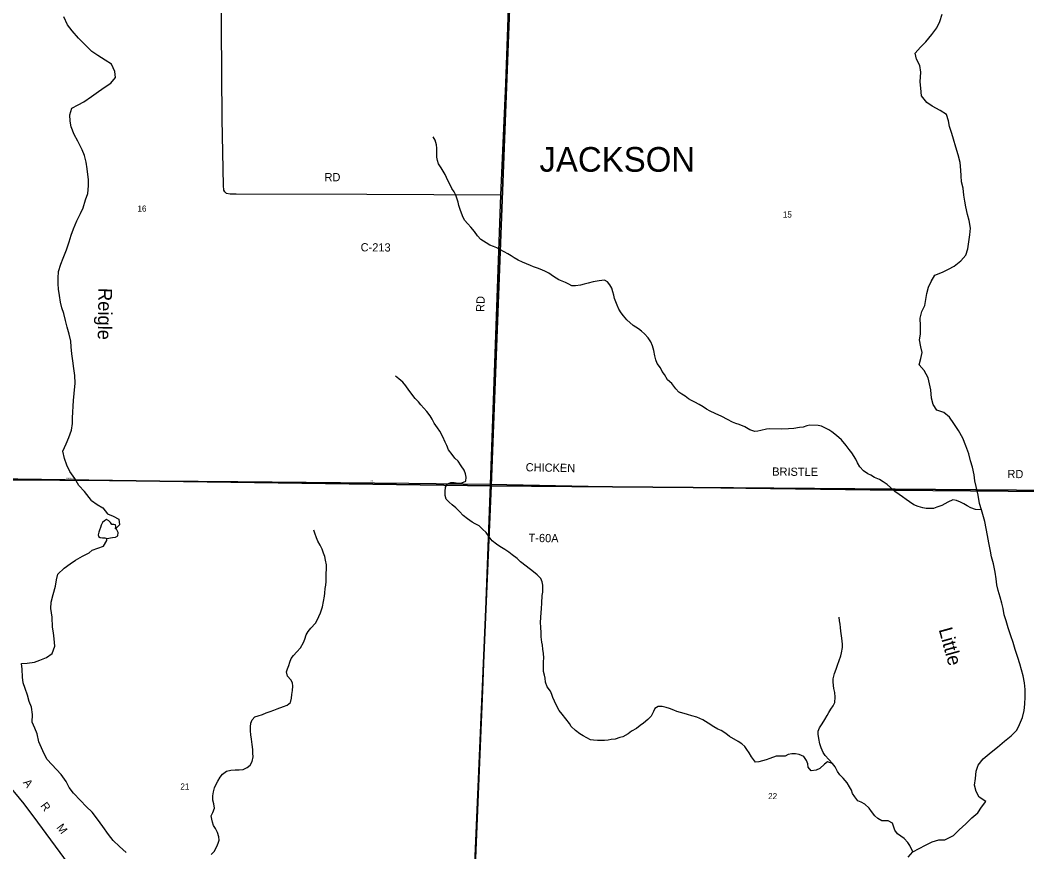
# Model space of a CAD drawing. Extents: x 1312308 to 1684953, y 460642 to 865172.
# Drawn here: x 1422870 to 1432056, y 621406 to 628989 of the extents above; entities that cross this region are included whole.
import ezdxf

# ---------------------------------------------------------------- set-up
doc = ezdxf.new("R2010")
doc.units = 0
for name, color, linetype in [('GM_X_County_Road', 7, 'Continuous'), ('GM_X_County_Road_Text', 7, 'Continuous'), ('GM_X_Minor_Lake', 7, 'Continuous'), ('GM_X_Minor_River', 7, 'Continuous'), ('GM_X_Minor_River_Text', 7, 'Continuous'), ('GM_X_Section', 7, 'Continuous'), ('GM_X_Section_Text', 7, 'Continuous'), ('GM_X_Township_Road', 7, 'Continuous'), ('GM_X_Township_Road_Text', 7, 'Continuous'), ('GM_X_Township_Subdivision', 7, 'Continuous'), ('GM_X_Township_Subdivision_Text', 7, 'Continuous'), ('GM_X_Township_Text', 7, 'Continuous')]:
    doc.layers.add(name, color=color, linetype=linetype)

msp = doc.modelspace()

# ---------------------------------------------------------------- linework, layer by layer
at = {"layer": 'GM_X_County_Road'}
for points in [[(1427257.5, 627393.2), (1426034, 627399.5), (1424841.7, 627402.6), (1424785.8, 627402), (1424754, 627408.7), (1424737.3, 627422.5), (1424728.2, 627437.8), (1424725.9, 627481), (1424712.3, 628086), (1424706.1, 628920.6), (1424700.1, 629955.3), (1424702.4, 630572.3), (1424735.3, 632468.4), (1424764.9, 634127), (1424816.2, 638179.6), (1424838.9, 639451.3), (1424867.3, 641453.3)], [(1426953, 619489.3), (1426952.1, 619516.1), (1426971.2, 619931.5), (1426996.8, 620555.9), (1427022.4, 621198.4), (1427091.4, 622876.4), (1427163, 624758.3), (1427257.5, 627393.2), (1427300.3, 628410.2), (1427360.9, 630040.4), (1427420.8, 632760.9), (1427452.2, 634128.6), (1427497.7, 636658.4), (1427531.5, 637964.6), (1427563.2, 639629.6), (1427575.5, 640318.2)], [(1425178.7, 618809.3), (1424819, 619478.2), (1424794.1, 619513.9), (1424735.3, 619588.9), (1424329.4, 620045.2), (1423843.4, 620590.6), (1423757, 620693.6), (1423588.3, 620906.4), (1423489.2, 621043.8), (1423309.8, 621294.9), (1423031.7, 621676.5), (1422907.5, 621844.7), (1422721.8, 622068.1), (1422500.6, 622334.6), (1422184.3, 622710.6), (1421710.1, 623249.4), (1421491.7, 623491.9), (1421228.6, 623784.4), (1420620.9, 624439.9), (1420252.3, 624831.1), (1420094.1, 624993.7), (1420031.9, 625057)]]:
    msp.add_lwpolyline(points, dxfattribs=at)
at = {"layer": 'GM_X_Minor_Lake'}
for points in [[(1423739.7, 624350.6), (1423742.1, 624372.6), (1423740.4, 624388.7), (1423724.5, 624391), (1423706.4, 624391.4), (1423692.8, 624409.7), (1423679, 624424.1), (1423659.2, 624434.5), (1423638.9, 624422.9), (1423622.5, 624407.3), (1423610, 624383.5), (1423601.5, 624361.6), (1423595.1, 624339.7), (1423586.6, 624319.8), (1423582.1, 624295.8), (1423585.9, 624281.7), (1423599.7, 624271.4), (1423621.7, 624268.9), (1423641.7, 624268.5), (1423659.7, 624264.1)], [(1423659.7, 624264.1), (1423711.9, 624271), (1423740.1, 624274.4), (1423762.4, 624287.9), (1423763, 624316), (1423747.6, 624348.4), (1423739.7, 624350.6)]]:
    msp.add_lwpolyline(points, dxfattribs=at)
at = {"layer": 'GM_X_Minor_River'}
for points in [[(1423520.2, 624609.8), (1423458.2, 624691.8), (1423405.6, 624745.7), (1423369.5, 624809.2), (1423323.3, 624875), (1423294.9, 624930.1), (1423274.7, 624991), (1423260.7, 625057.8), (1423289, 625127.1), (1423314.8, 625182.5), (1423339, 625249.9), (1423349, 625311.8), (1423346.5, 625362.1), (1423357.5, 625520.4), (1423361.5, 625584.5), (1423372.5, 625678.5), (1423368.6, 625748.9), (1423360.5, 625811.4), (1423350.8, 625884), (1423342.7, 625946.5), (1423336.6, 626011), (1423332.3, 626063.3), (1423318.1, 626126), (1423300.1, 626190.8), (1423283.9, 626251.6), (1423267.8, 626314.4), (1423251.3, 626365.1), (1423236.9, 626417.8), (1423228.7, 626478.3), (1423218.4, 626534.8), (1423216, 626585.1), (1423215.6, 626637.3), (1423219.5, 626697.4), (1423239.6, 626763), (1423261.4, 626818.5), (1423293.9, 626893.7), (1423316.3, 626967.2), (1423334.2, 627028.9), (1423356.1, 627086.4), (1423388.5, 627157.6), (1423420.7, 627224.8), (1423444.4, 627276.2), (1423466.8, 627349.7), (1423486.7, 627409.3), (1423494.8, 627477.3), (1423494.6, 627533.5), (1423481.7, 627634.3), (1423471.5, 627694.8), (1423457.3, 627753.5), (1423436.8, 627806.4), (1423395, 627884), (1423362.9, 627947.3), (1423334.9, 628016.5), (1423326.4, 628066.9), (1423324.2, 628125.2), (1423342.2, 628184.8), (1423399.4, 628217.1), (1423452.4, 628243.4), (1423522.2, 628291.3), (1423586, 628339.4), (1423645.5, 628379.5), (1423698.8, 628413.9), (1423738.6, 628466.8), (1423734.2, 628519.1), (1423702.2, 628588.4), (1423645.1, 628624.4), (1423580.1, 628666.7), (1423523, 628702.7), (1423456.8, 628771.1), (1423402.3, 628825.1), (1423344.1, 628891.3), (1423301.6, 628944.9), (1423267.8, 629020.2)], [(1431078.5, 628575), (1431048.2, 628632.2), (1431037.8, 628686.7), (1431085.7, 628741.3), (1431135.5, 628791.9), (1431187.8, 628858.4), (1431235.9, 628919.1), (1431261.8, 628976.4), (1431283.9, 629041.9)], [(1431912.1, 622462.2), (1431966, 622514.7), (1431987.6, 622566.2), (1432015.8, 622631.6), (1432031.8, 622695.4), (1432037.7, 622753.4), (1432041.7, 622817.6), (1432041.8, 622885.9), (1432035.7, 622946.3), (1432023.6, 623009), (1431990.8, 623118.6), (1431974.6, 623177.3), (1431950.8, 623250.4), (1431932.6, 623313.3), (1431910.4, 623374.3), (1431886.7, 623449.4), (1431866.6, 623512.3), (1431850.2, 623567), (1431839.9, 623623.6), (1431827.4, 623674.2), (1431813.1, 623728.9), (1431794.9, 623789.8), (1431782.4, 623840.4), (1431776.1, 623894.8), (1431765.9, 623955.4), (1431750.2, 624032.2), (1431734.2, 624097), (1431725.7, 624147.5), (1431710, 624222.3), (1431696, 624291.1), (1431685.9, 624353.7), (1431671.9, 624418.4), (1431643.1, 624523.8), (1431624.7, 624580.6), (1431613.1, 624657.2), (1431593.5, 624738.2), (1431581, 624788.8), (1431574.7, 624843.2), (1431558.8, 624914), (1431540.5, 624970.9), (1431526.5, 625035.6), (1431500.6, 625106.7), (1431470.7, 625177.9), (1431432.7, 625247.5), (1431390.5, 625311.1), (1431350.1, 625368.6), (1431299.2, 625410.4), (1431235.6, 625432.6), (1431201.1, 625483.9), (1431184.7, 625540.7), (1431181.1, 625617.1), (1431166.7, 625671.8), (1431156.5, 625728.3), (1431120.3, 625793.7), (1431073.8, 625845.4), (1431087.7, 625905.2), (1431099.3, 625957), (1431088.9, 626009.6), (1431074.9, 626074.3), (1431084.5, 626126.1), (1431086.9, 626202.3), (1431083, 626270.7), (1431099, 626332.4), (1431124.8, 626387.8), (1431142.3, 626497.6), (1431158.2, 626555.3), (1431183.9, 626606.7), (1431215.8, 626663.8), (1431284.9, 626689.7), (1431340, 626718), (1431393.1, 626746.4), (1431452.8, 626794.6), (1431500.6, 626845.2), (1431518.4, 626902.8), (1431534.5, 627030.8), (1431540.4, 627092.8), (1431530.6, 627163.4), (1431514.2, 627216.1), (1431498.3, 627286.9), (1431489.8, 627337.3), (1431481.5, 627391.8), (1431473.4, 627456.3), (1431459.2, 627514.9), (1431456.9, 627569.2), (1431454.5, 627621.5), (1431448.6, 627689.9), (1431430.7, 627760.7), (1431406.8, 627829.8), (1431386.9, 627902.7), (1431370.5, 627955.4), (1431350.4, 628020.3), (1431340, 628070.8), (1431323.7, 628129.5), (1431264.6, 628165.6), (1431193.5, 628204), (1431142.3, 628237.8), (1431096, 628297.5), (1431088.2, 628370), (1431083.9, 628426.3), (1431088.7, 628514.5), (1431078.5, 628575)], [(1428201, 626618.3), (1428154.8, 626613.1), (1428098.4, 626602.1), (1428054, 626590.9), (1428017.8, 626581.5), (1427983.5, 626572.1), (1427937.2, 626564.9), (1427905.1, 626567.5), (1427875.3, 626582.1), (1427847.6, 626596.7), (1427815.7, 626609.3), (1427785.9, 626621.9), (1427736.4, 626652.9), (1427694.9, 626681.8), (1427663.1, 626698.4), (1427629.3, 626713.1), (1427591.5, 626727.8), (1427555.6, 626738.5), (1427527.8, 626751.1), (1427490, 626767.8), (1427454.2, 626782.6), (1427414.4, 626799.4), (1427376.8, 626822.1), (1427349.1, 626838.7), (1427319.4, 626857.3), (1427285.6, 626876), (1427248, 626896.8), (1427218.2, 626911.4), (1427188.3, 626924), (1427154.5, 626938.6), (1427122.9, 626959.3), (1427073.3, 626988.3), (1427043.9, 627023), (1427014.6, 627061.6), (1426983.3, 627100.3), (1426955.9, 627133), (1426924.5, 627165.7), (1426907.3, 627206.1), (1426886.4, 627262.7), (1426873.1, 627299.1), (1426865.7, 627329.3), (1426858.2, 627357.6), (1426844.9, 627391.9), (1426831.5, 627422.3), (1426810.1, 627454.8), (1426792.7, 627487.2), (1426779.2, 627515.6), (1426760, 627554), (1426748.5, 627582.4), (1426729.1, 627612.8), (1426711.6, 627641.2), (1426688.3, 627679.8), (1426676.9, 627710.1), (1426673.5, 627740.3), (1426672.4, 627782.4), (1426671.1, 627820.6), (1426667.7, 627850.8), (1426656.6, 627895.1), (1426639.1, 627923.5)], [(1431643.1, 624523.8), (1431586.1, 624526.5), (1431544.3, 624541.3), (1431510.6, 624562), (1431480.9, 624578.6), (1431449.1, 624595.3), (1431415.3, 624607.9), (1431381.3, 624614.6), (1431334.7, 624593.3), (1431280, 624564.2), (1431233.5, 624547), (1431203.2, 624535.5), (1431137, 624536.7), (1431107.1, 624543.3), (1431065.2, 624554.1), (1431025.4, 624570.9), (1430985.8, 624597.7), (1430954.2, 624618.4), (1430920.5, 624641.1), (1430890.9, 624663.7), (1430851.3, 624690.6), (1430812, 624727.4), (1430782.4, 624754.1), (1430744.8, 624778.8), (1430711.2, 624799.5), (1430665.4, 624818.5), (1430631.8, 624841.2), (1430603.9, 624853.7), (1430564.3, 624878.5), (1430531, 624915.3), (1430509.7, 624953.8), (1430494.3, 624986.2), (1430459.4, 625043.1), (1430436, 625075.6), (1430408.6, 625110.3), (1430363.6, 625163.3), (1430320.3, 625202.2), (1430276.8, 625235.2), (1430249.1, 625253.7), (1430219.3, 625268.3), (1430181.6, 625287.1), (1430151.6, 625293.7), (1430075.4, 625295.1), (1430047.2, 625289.5), (1430014.9, 625278.1), (1429980.7, 625274.7), (1429930.4, 625265.6), (1429880.2, 625262.5), (1429818, 625259.6), (1429711.7, 625261.6), (1429679.6, 625260.2), (1429629.2, 625247), (1429601, 625241.5), (1429572.8, 625238), (1429529, 625252.9), (1429483.4, 625279.8), (1429429.7, 625302.9), (1429401.8, 625311.4), (1429370, 625324.1), (1429324.3, 625347), (1429272.7, 625374.1), (1429211.1, 625403.3), (1429165.4, 625424.2), (1429133.7, 625442.9), (1429102.1, 625463.5), (1429066.4, 625484.2), (1429026.7, 625505), (1428994.9, 625519.7), (1428967.2, 625536.3), (1428937.5, 625558.9), (1428907.8, 625577.5), (1428880.2, 625598.1), (1428852.7, 625628.7), (1428815.6, 625675.5), (1428776.2, 625710.4), (1428749, 625757.1), (1428729.6, 625785.5), (1428712.2, 625818), (1428682.9, 625858.7), (1428669.6, 625893), (1428662.3, 625929.3), (1428653.2, 625975.6), (1428640, 626018), (1428624.7, 626054.4), (1428599.5, 626093), (1428568.1, 626127.8), (1428538.5, 626152.4), (1428510.8, 626173), (1428463.4, 626205.9), (1428406.3, 626257.2), (1428376.9, 626291.9), (1428353.4, 626320.4), (1428332, 626354.9), (1428316.7, 626389.3), (1428293.9, 626452), (1428286.5, 626482.2), (1428277, 626510.5), (1428267.7, 626544.8), (1428250.3, 626575.2), (1428228.8, 626603.7), (1428201, 626618.3)], [(1427638.6, 623838.1), (1427633.2, 623866.3), (1427619.8, 623898.7), (1427588.4, 623931.4), (1427552.8, 623960.2), (1427487.7, 624009.5), (1427436.4, 624050.7), (1427404.9, 624081.3), (1427359.4, 624114.3), (1427327.8, 624139), (1427292.2, 624161.7), (1427246.6, 624188.7), (1427217, 624211.3), (1427177.5, 624240.2), (1427148.1, 624276.8), (1427122.9, 624317.5), (1427089.4, 624348.2), (1427057.9, 624376.9), (1427022.2, 624395.6), (1426994.5, 624412.2), (1426950.9, 624441.1), (1426911.4, 624471.9), (1426880.1, 624508.7), (1426844.7, 624543.5), (1426813.1, 624568.1), (1426785.5, 624592.7), (1426758, 624621.4), (1426748.7, 624655.7), (1426747.5, 624691.8), (1426752.3, 624731.9), (1426768.9, 624761.7), (1426799.3, 624773.2), (1426829.3, 624772.6), (1426865.3, 624765.9), (1426901.5, 624769.3), (1426935.9, 624786.7), (1426940.6, 624820.8), (1426933.3, 624853), (1426921.9, 624885.4), (1426892.7, 624926.1), (1426867.4, 624966.7), (1426835.9, 624995.4), (1426810.5, 625027.9), (1426777.3, 625070.7), (1426762, 625109.2), (1426746.6, 625139.6), (1426727.6, 625190.1), (1426700.5, 625240.8), (1426679.1, 625271.3), (1426647.9, 625314), (1426630.6, 625350.5), (1426611.1, 625381), (1426579.8, 625419.7), (1426554.4, 625452.3), (1426524.9, 625480.9), (1426505.5, 625509.4), (1426474, 625538.1), (1426415.4, 625615.4), (1426388.1, 625654.1), (1426360.7, 625688.7), (1426325.2, 625719.5), (1426295.6, 625744.1)], [(1423520.2, 624609.8), (1423573.8, 624572.8), (1423625.4, 624543.5), (1423666.3, 624488.5), (1423718, 624465.3), (1423769.5, 624438.2), (1423776.5, 624387.9), (1423739.7, 624350.6)], [(1425658.8, 623838.5), (1425661.5, 623870.6), (1425662.1, 623900.7), (1425661, 623944.9), (1425663.8, 623983), (1425664.6, 624021.2), (1425657.5, 624065.5), (1425650.2, 624099.7), (1425638.7, 624128.1), (1425625.4, 624164.4), (1425608.1, 624200.9), (1425586.8, 624239.5), (1425573.4, 624269.8), (1425558.2, 624310.3), (1425548.7, 624338.5)], [(1423527.4, 624156.2), (1423577.6, 624175.6), (1423630.1, 624192.5), (1423659.3, 624243.7), (1423659.7, 624264.1)], [(1423376.4, 624065.9), (1423437.8, 624102.1), (1423499, 624132.2), (1423527.4, 624156.2)], [(1423837.5, 621399.6), (1423774.9, 621455.9), (1423718.3, 621507.9), (1423675.9, 621563.6), (1423624, 621637.6), (1423575.8, 621703.5), (1423525.6, 621767.4), (1423473, 621819.3), (1423420.5, 621875.3), (1423356.3, 621941.7), (1423315.7, 621993.2), (1423289.3, 622048.3), (1423243.1, 622112.1), (1423116.8, 622246.8), (1423088.3, 622298), (1423065.9, 622355), (1423039.5, 622408.1), (1423023.7, 622480.9), (1423005.2, 622533.7), (1422978.8, 622586.8), (1422981, 622659.1), (1422973.1, 622725.6), (1422950.6, 622776.6), (1422938.3, 622835.2), (1422916.1, 622896.2), (1422897.6, 622947), (1422891.2, 622999.4), (1422889.4, 623069.8), (1422883, 623122.2), (1422935.3, 623124.5), (1422999.9, 623136.5), (1423050.7, 623152.9), (1423109.7, 623179), (1423163, 623213.4), (1423187.2, 623280.9), (1423179.3, 623347.4), (1423173, 623403.9), (1423166.5, 623454.3), (1423163.3, 623544.8), (1423149.7, 623623.6), (1423151.5, 623681.8), (1423171.8, 623751.4), (1423192.3, 623829), (1423200, 623885), (1423213.8, 623938.8), (1423271.6, 623991.1), (1423325.1, 624031.5), (1423376.4, 624065.9)], [(1424613.6, 621381.8), (1424640.2, 621409.4), (1424665.2, 621453.1), (1424677.9, 621485), (1424684.5, 621513), (1424683, 621541.2), (1424671.9, 621583.5), (1424652.5, 621618), (1424633.1, 621646.5), (1424625.6, 621674.8), (1424618.2, 621703), (1424612.8, 621735.3), (1424629.4, 621763.1), (1424642.3, 621803), (1424637.1, 621843.3), (1424627.7, 621875.6), (1424628.5, 621915.7), (1424635.3, 621953.8), (1424642.1, 621989.8), (1424654.7, 622017.7), (1424673.4, 622049.5), (1424694.2, 622087.2), (1424714.9, 622115), (1424753.5, 622142.4), (1424791.8, 622151.7), (1424832, 622153), (1424868.1, 622154.3), (1424904.3, 622157.6), (1424940.8, 622175), (1424969.3, 622196.6), (1424988, 622230.4), (1424994.9, 622272.4), (1424993.6, 622304.6), (1424992.2, 622338.8), (1424987.1, 622383), (1424980.1, 622433.4), (1424975, 622473.6), (1424971.7, 622509.8), (1424970.4, 622544), (1424975.1, 622578.1), (1424985.7, 622608), (1425010.4, 622635.7), (1425040.7, 622647.1), (1425081, 622658.4), (1425115.4, 622671.9), (1425151.8, 622685.2), (1425186.1, 622696.7), (1425216.5, 622708.1), (1425273.1, 622731.2), (1425305.4, 622742.7), (1425336, 622766.2), (1425344.8, 622806.2), (1425349.5, 622840.2), (1425354.3, 622876.3), (1425357.1, 622916.4), (1425353.7, 622946.6), (1425340.3, 622975), (1425310.9, 623007.6), (1425301.6, 623046), (1425308.2, 623073.9), (1425320.9, 623105.8), (1425329.5, 623135.8), (1425342.2, 623167.7), (1425362.9, 623197.4), (1425393.6, 623229), (1425428.4, 623264.5), (1425455.5, 623314.2), (1425466.2, 623346.1), (1425481, 623384), (1425497.7, 623415.8), (1425522.4, 623445.5), (1425565.5, 623490.9), (1425584.2, 623524.7), (1425596.8, 623552.5), (1425611.5, 623584.4), (1425628.7, 623640.3), (1425646.7, 623736.4), (1425649.3, 623764.4), (1425654.2, 623806.5), (1425658.8, 623838.5)], [(1430283, 622210.8), (1430237.2, 622227.7), (1430208.6, 622204.1), (1430165.7, 622166.8), (1430133.3, 622149.3), (1430089.1, 622144.1), (1430061.6, 622176.7), (1430056.2, 622207), (1430044.9, 622239.3), (1430021.6, 622275.9), (1429979.8, 622294.7), (1429945.8, 622299.4), (1429911.7, 622300), (1429879.5, 622292.6), (1429849.1, 622279.1), (1429809, 622277.8), (1429768.9, 622278.5), (1429710.3, 622257.5), (1429677.9, 622246.1), (1429643.6, 622234.7), (1429609.3, 622225.2), (1429579.2, 622223.8), (1429542.1, 622272.7), (1429520.7, 622307.2), (1429501.3, 622337.7), (1429481.8, 622366.2), (1429454.3, 622390.8), (1429420.6, 622411.5), (1429341.3, 622457.2), (1429307.7, 622483.9), (1429266.2, 622510.8), (1429236.3, 622523.3), (1429200.7, 622544.1), (1429147.2, 622579.2), (1429099.7, 622610.2), (1429046, 622633.3), (1429000.2, 622646.2), (1428960.3, 622657), (1428930.4, 622665.6), (1428896.5, 622676.2), (1428862.6, 622684.9), (1428834.7, 622697.5), (1428794.9, 622712.2), (1428765.1, 622722.8), (1428729.1, 622731.5), (1428693, 622730.2), (1428662.6, 622712.7), (1428649.9, 622684.8), (1428629, 622643), (1428596.3, 622611.5), (1428557.5, 622580.1), (1428527, 622558.5), (1428494.3, 622531), (1428449.7, 622505.7), (1428417.1, 622480.2), (1428370.4, 622455), (1428342.2, 622447.5), (1428299.8, 622434.2), (1428263.6, 622428.8), (1428235.4, 622425.3), (1428203.3, 622421.9), (1428175.2, 622420.4), (1428137.1, 622421.1), (1428101, 622423.8), (1428073, 622428.3), (1428041.3, 622445), (1428007.6, 622463.7), (1427977.9, 622482.3), (1427938.3, 622511.2), (1427899, 622548), (1427883.5, 622576.4), (1427848.3, 622619.3), (1427815.1, 622662), (1427789.7, 622694.7), (1427760.6, 622747.4), (1427729.9, 622812.2), (1427722.4, 622840.5), (1427709, 622870.9), (1427679.8, 622911.6), (1427664.6, 622954), (1427659.3, 622988.3), (1427653.8, 623016.5), (1427646.5, 623050.8), (1427645.3, 623086.9), (1427646.3, 623137.1), (1427649.1, 623175.2), (1427645.9, 623215.4), (1427640.7, 623253.7), (1427635.4, 623289.9), (1427629.9, 623318.2), (1427624.9, 623366.4), (1427623.6, 623400.6), (1427620.7, 623456.9), (1427619.5, 623493), (1427620.6, 623545.2), (1427626.2, 623625.5), (1427629.2, 623671.6), (1427634.7, 623743.8), (1427639.3, 623773.8), (1427639.9, 623803.9), (1427638.6, 623838.1)], [(1431015.6, 621406.8), (1430987.7, 621462.6), (1430970.2, 621491.1), (1430936.9, 621527.8), (1430907.2, 621548.5), (1430875.6, 621571.2), (1430850.2, 621603.8), (1430840.8, 621632.1), (1430831.4, 621666.4), (1430789.8, 621689.2), (1430761.7, 621689.8), (1430733.6, 621688.3), (1430695.9, 621709.1), (1430668.3, 621733.7), (1430639.1, 621774.4), (1430615.6, 621802.9), (1430576.2, 621839.8), (1430544.5, 621858.5), (1430514.7, 621871.1), (1430487.4, 621907.8), (1430465.9, 621938.3), (1430454.5, 621966.6), (1430437.1, 621999.1), (1430415.7, 622033.6), (1430380.6, 622078.4), (1430349.1, 622109.2), (1430327.6, 622137.7), (1430306.4, 622180.2), (1430283, 622210.8), (1430249.6, 622247.6), (1430214.3, 622284.4), (1430196.8, 622312.8), (1430179.6, 622353.3), (1430168.3, 622391.7), (1430159.3, 622438), (1430152.1, 622478.4), (1430152.6, 622506.5), (1430165.3, 622536.4), (1430188.1, 622572.1), (1430213, 622611.8), (1430233.8, 622647.6), (1430248.4, 622675.4), (1430267, 622705.2), (1430287.8, 622737), (1430302.4, 622766.8), (1430305.4, 622815), (1430302.3, 622857.2), (1430295, 622895.5), (1430288.2, 622951.9), (1430288.8, 622982), (1430301.8, 623031.9), (1430314.6, 623069.9), (1430329.5, 623107.8), (1430344.4, 623149.7), (1430357.3, 623191.6), (1430365.9, 623221.5), (1430372.9, 623267.6), (1430373.4, 623295.7), (1430370.1, 623329.9), (1430365.1, 623376.2), (1430357.9, 623416.5), (1430354.5, 623450.7), (1430351.2, 623480.9), (1430345.8, 623513.1), (1430342.4, 623545.3)], [(1430971.8, 621355.9), (1431015.6, 621406.8), (1431072.7, 621437), (1431131.9, 621467.2), (1431193.1, 621497.4), (1431251.9, 621515.5), (1431306.2, 621515.8), (1431387.7, 621553.3), (1431439.6, 621607.8), (1431499.5, 621662.1), (1431555.4, 621714.5), (1431609, 621761), (1431640.8, 621812.2), (1431680.6, 621865.1), (1431619.6, 621905.3), (1431593.1, 621956.4), (1431578.8, 622013.1), (1431586.7, 622075.1), (1431594.8, 622141.2), (1431612.5, 622194.8), (1431656.6, 622253.7), (1431730.8, 622315.5), (1431788.4, 622359.8), (1431852.3, 622414), (1431912.1, 622462.2)]]:
    msp.add_lwpolyline(points, dxfattribs=at)
at = {"layer": 'GM_X_Section'}
for points in [[(1422017.8, 630093.9), (1427370.7, 630042.9), (1427168.8, 624743.3), (1421982.3, 624814.7)], [(1427370.7, 630042.9), (1432755.4, 629989.2), (1432697.6, 624696.5), (1427168.8, 624743.3)], [(1427168.8, 624743.3), (1426939.4, 619468.3), (1421948.9, 619535.5), (1421982.3, 624814.7)], [(1432697.6, 624696.5), (1432643.4, 619381.8), (1426939.4, 619468.3), (1427168.8, 624743.3)]]:
    msp.add_lwpolyline(points, close=True, dxfattribs=at)
at = {"layer": 'GM_X_Township_Road'}
msp.add_lwpolyline([(1427163, 624758.3), (1428201.4, 624735.5), (1429036.5, 624727.9), (1430853.3, 624703), (1431884.2, 624695.4), (1432694.8, 624686)], dxfattribs=at)
at = {"layer": 'GM_X_Township_Subdivision'}
msp.add_lwpolyline([(1420252.3, 624831.1), (1420925.5, 624820.9), (1422781.8, 624798.1), (1424135.5, 624789), (1424856.5, 624782), (1426415.3, 624768), (1427163, 624758.3)], dxfattribs=at)

# ---------------------------------------------------------------- texts
at = {"layer": 'GM_X_County_Road_Text'}
for s, rotation, p in [('RD', 0.00001, (1425647.4, 627519.6)), ('C-213', 359.72295, (1425977, 626880.4)), ('RD', 88.02522, (1427104.7, 626327.7)), ('A', 306.74429, (1422892.7, 622036.2)), ('R', 306.74382, (1423050.6, 621824.6)), ('M', 306.74423, (1423198, 621627.2))]:
    msp.add_text(s, height=75, rotation=rotation, dxfattribs=at).set_placement(p)
at = {"layer": 'GM_X_Minor_River_Text'}
for s, height, rotation, p in [('Reigle', 125.04, 269.17193, (1423584.4, 626547.8)), ('Little', 125.08, 285.45382, (1431250.7, 623433.3))]:
    msp.add_text(s, height=height, rotation=rotation, dxfattribs=at).set_placement(p)
at = {"layer": 'GM_X_Section_Text'}
for s, p in [('16', (1423940.2, 627243.5)), ('15', (1429829.6, 627189.1)), ('21', (1424331.8, 621974)), ('22', (1429695.4, 621886))]:
    msp.add_text(s, height=55.25, rotation=0.00001, dxfattribs=at).set_placement(p)
at = {"layer": 'GM_X_Township_Road_Text'}
for s, rotation, p in [('CHICKEN', 358.92221, (1427482.3, 624875.2)), ('BRISTLE', 359.5056, (1429732.2, 624835.7)), ('RD', 359.50636, (1431878.8, 624813.6)), ('T-60A', 358.97058, (1427508.9, 624231.8))]:
    msp.add_text(s, height=75, rotation=rotation, dxfattribs=at).set_placement(p)
at = {"layer": 'GM_X_Township_Subdivision_Text'}
for s, rotation, p in [('BRISTLE', 359.13243, (1423293.5, 624806.2)), ('RD', 0.00001, (1426065.4, 624779.8))]:
    msp.add_text(s, height=12.5, rotation=rotation, dxfattribs=at).set_placement(p)
at = {"layer": 'GM_X_Township_Text'}
msp.add_text('JACKSON', height=225, rotation=0.00001, dxfattribs=at).set_placement((1427608.4, 627606.7))

doc.saveas('drawing.dxf')
